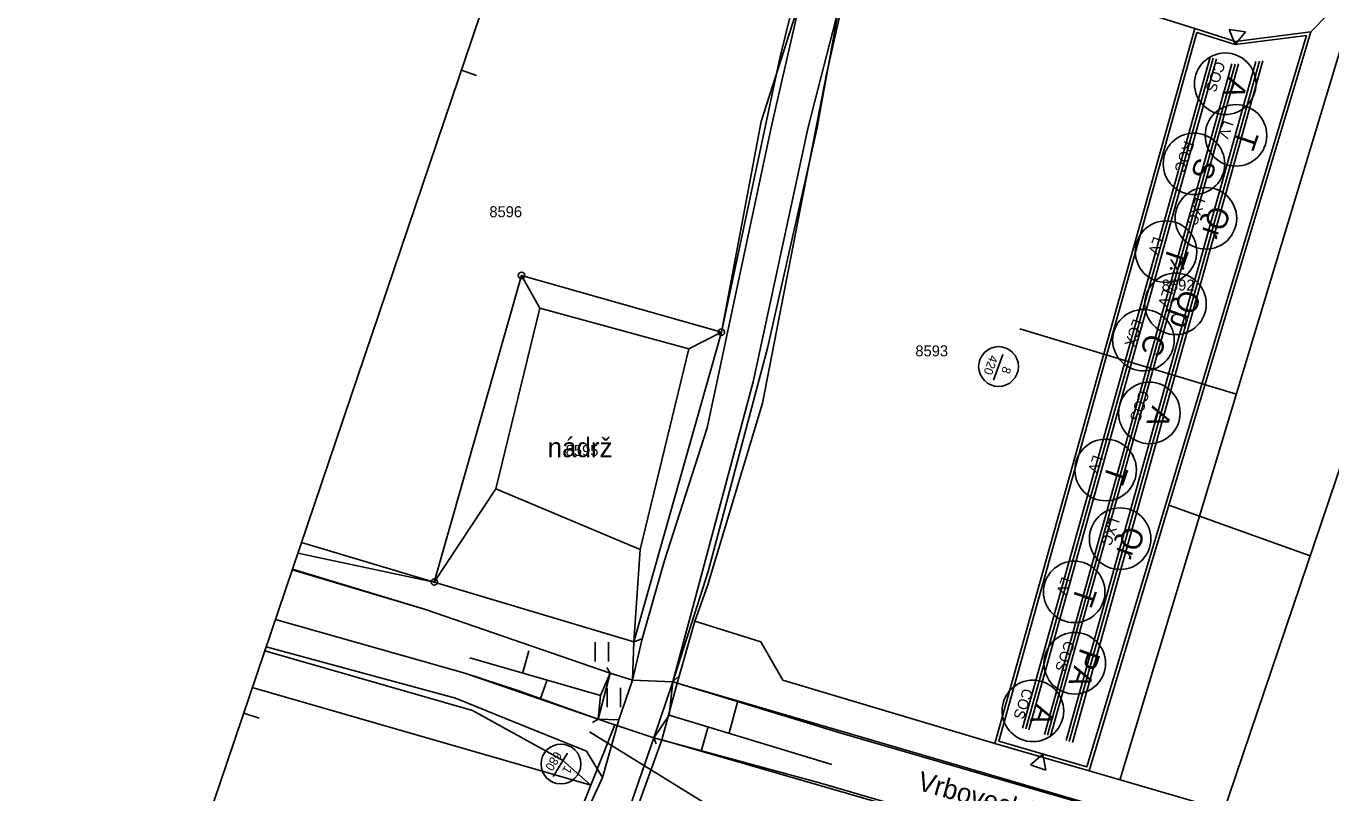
# Model space of a CAD drawing. Extents: x -639348 to -639039, y -1201065 to -1200521.
# Drawn here: x -639348.5 to -639146.6, y -1200930.7 to -1200812.1 of the extents above; entities that cross this region are included whole.
import ezdxf

# ---------------------------------------------------------------- set-up
doc = ezdxf.new("R2010")
doc.units = 0
for name, color, linetype in [('Hranice kat_ území', 7, 'Continuous'), ('Obvody jako plochy', 7, 'Continuous'), ('plot', 7, 'Continuous'), ('stromy', 7, 'Continuous'), ('trojrady', 7, 'Continuous'), ('tráva', 7, 'Continuous'), ('Vrstva 15', 7, 'Continuous'), ('Vrstva 18', 7, 'Continuous'), ('Vrstva 24', 7, 'Continuous'), ('Vrstva 25', 7, 'Continuous'), ('Vrstva 26', 7, 'Continuous'), ('Vrstva 43', 7, 'Continuous'), ('Vrstva 44', 7, 'Continuous'), ('Vrstva 45', 7, 'Continuous'), ('Vrstva 47', 7, 'Continuous'), ('Vrstva 48', 7, 'Continuous'), ('Vrstva 62', 7, 'Continuous'), ('Vrstva 63', 7, 'Continuous'), ('značky', 7, 'Continuous'), ('ŘEŠENÉ', 7, 'Continuous')]:
    doc.layers.add(name, color=color, linetype=linetype)

msp = doc.modelspace()

# ---------------------------------------------------------------- linework, layer by layer
at = {"layer": 'Hranice kat_ území'}
for p, q in [((-639259.95, -1200919.32), (-639258.12, -1200912.21)), ((-639248.38, -1200913.54), (-639251.32, -1200922.19))]:
    msp.add_line(p, q, dxfattribs=at)
at = {"layer": 'Obvody jako plochy'}
for p, q in [((-639167.64, -1200812.46), (-639207.36, -1200799.96)), ((-639229.15, -1200805.96), (-639231.84, -1200817.07)), ((-639142.08, -1200805.09), (-639149.66, -1200812.96)), ((-639222.04, -1200808.14), (-639224.6, -1200819.52)), ((-639198.57, -1200923.08), (-639167.64, -1200812.46)), ((-639149.66, -1200812.96), (-639171.65, -1200886.21)), ((-639167.64, -1200812.46), (-639161.32, -1200814.45)), ((-639161.32, -1200814.45), (-639149.66, -1200812.96)), ((-639231.84, -1200817.07), (-639240.89, -1200859.46)), ((-639224.6, -1200819.52), (-639234.5, -1200870.43)), ((-639271.82, -1200850.66), (-639285.31, -1200898.1)), ((-639240.89, -1200859.46), (-639271.82, -1200850.66)), ((-639254.43, -1200907.37), (-639240.89, -1200859.46)), ((-639234.5, -1200870.43), (-639243.04, -1200898.7)), ((-639184, -1200927.32), (-639171.65, -1200886.21)), ((-639171.65, -1200886.21), (-639149.78, -1200894.03)), ((-639285.31, -1200898.1), (-639305.87, -1200892)), ((-639307.3, -1200896.22), (-639286.68, -1200902.33)), ((-639285.31, -1200898.1), (-639254.43, -1200907.37)), ((-639243.04, -1200898.7), (-639245.01, -1200904.18)), ((-639286.68, -1200902.33), (-639258.12, -1200912.21)), ((-639309.89, -1200903.88), (-639280.61, -1200912.21)), ((-639245.01, -1200904.18), (-639247.74, -1200913.73)), ((-639245.01, -1200904.18), (-639234.76, -1200907.38)), ((-639254.43, -1200907.37), (-639254.64, -1200913.28)), ((-639234.76, -1200907.38), (-639231.36, -1200913.29)), ((-639279.41, -1200918), (-639311.54, -1200908.75)), ((-639280.61, -1200912.21), (-639259.95, -1200919.32)), ((-639254.64, -1200913.28), (-639258.12, -1200912.21)), ((-639254.64, -1200913.28), (-639248.38, -1200913.54)), ((-639247.74, -1200913.73), (-639250.09, -1200922.53)), ((-639248.38, -1200913.54), (-639247.74, -1200913.73)), ((-639247.74, -1200913.73), (-639164.68, -1200938.04)), ((-639231.36, -1200913.29), (-639198.57, -1200923.08)), ((-639261.1, -1200929.51), (-639313.47, -1200914.44)), ((-639265.47, -1200925.64), (-639279.41, -1200918)), ((-639259.95, -1200919.32), (-639257.38, -1200920.18)), ((-639257.38, -1200920.18), (-639261.1, -1200929.51)), ((-639251.32, -1200922.19), (-639257.38, -1200920.18)), ((-639253.49, -1200931.95), (-639250.09, -1200922.53)), ((-639251.32, -1200922.19), (-639250.09, -1200922.53)), ((-639250.09, -1200922.53), (-639167.48, -1200946.33)), ((-639184, -1200927.32), (-639198.57, -1200923.08)), ((-639261.1, -1200929.51), (-639265.47, -1200925.64)), ((-639163.1, -1200933.38), (-639184, -1200927.32)), ((-639261.1, -1200929.51), (-639263.57, -1200935.72))]:
    msp.add_line(p, q, dxfattribs=at)
at = {"layer": 'plot'}
for p, q in [((-639162.31, -1200812.6), (-639159.79, -1200812.97)), ((-639161.37, -1200814.96), (-639162.31, -1200812.6)), ((-639159.79, -1200812.97), (-639161.37, -1200814.96)), ((-639191.15, -1200924.72), (-639193.07, -1200926.38)), ((-639190.67, -1200927.22), (-639191.15, -1200924.72)), ((-639193.07, -1200926.38), (-639190.67, -1200927.22))]:
    msp.add_line(p, q, dxfattribs=at)
msp.add_lwpolyline([(-639167.3, -1200813.09), (-639161.37, -1200814.96), (-639150.36, -1200813.55), (-639172.13, -1200886.07), (-639184.34, -1200926.7), (-639197.96, -1200922.74)], close=True, dxfattribs=at)
at = {"layer": 'stromy'}
for centre in [(-639162.92, -1200821.01), (-639161.26, -1200829), (-639167.76, -1200833.4), (-639165.91, -1200841.83), (-639172.08, -1200846.99), (-639170.61, -1200855.07), (-639175.58, -1200860.68), (-639174.66, -1200871.94), (-639181.43, -1200880.77), (-639179.19, -1200891.4), (-639186.29, -1200899.63), (-639186.21, -1200910.67), (-639192.68, -1200918.04)]:
    msp.add_circle(centre, 4.76, dxfattribs=at)
at = {"layer": 'trojrady'}
for points in [[(-639194.27, -1200920.69), (-639165.24, -1200816.88)], [(-639193.79, -1200920.83), (-639164.77, -1200817.03)], [(-639193.31, -1200920.97), (-639164.29, -1200817.18)], [(-639190.91, -1200921.67), (-639161.9, -1200817.94)], [(-639190.43, -1200921.8), (-639161.4, -1200817.99)], [(-639189.95, -1200921.94), (-639160.86, -1200817.92)], [(-639187.55, -1200922.64), (-639158.17, -1200817.58)], [(-639187.07, -1200922.78), (-639157.63, -1200817.51)], [(-639186.58, -1200922.92), (-639157.09, -1200817.44)]]:
    msp.add_lwpolyline(points, dxfattribs=at)
at = {"layer": 'tráva'}
for p, q in [((-639167.64, -1200812.46), (-639198.57, -1200923.08)), ((-639171.65, -1200886.21), (-639149.66, -1200812.96)), ((-639161.32, -1200814.45), (-639167.64, -1200812.46)), ((-639149.66, -1200812.96), (-639161.32, -1200814.45)), ((-639184, -1200927.32), (-639171.65, -1200886.21)), ((-639198.57, -1200923.08), (-639184, -1200927.32))]:
    msp.add_line(p, q, dxfattribs=at)
at = {"layer": 'Vrstva 24'}
for centre, radius in [((-639271.82, -1200850.66), 0.5), ((-639271.82, -1200850.66), 0.0327), ((-639240.89, -1200859.46), 0.5), ((-639240.89, -1200859.46), 0.0327), ((-639285.31, -1200898.1), 0.5), ((-639285.31, -1200898.1), 0.0327)]:
    msp.add_circle(centre, radius, dxfattribs=at)
at = {"layer": 'Vrstva 25'}
for p, q in [((-639260.4, -1200907.4), (-639260.4, -1200910.4)), ((-639258.36, -1200910.4), (-639258.36, -1200907.4)), ((-639258.56, -1200914.48), (-639258.56, -1200917.48)), ((-639256.52, -1200917.48), (-639256.52, -1200914.48))]:
    msp.add_line(p, q, dxfattribs=at)
msp.add_lwpolyline([(-639169.36, -1200848.18), (-639170.36, -1200849.68), (-639171.36, -1200848.18)], dxfattribs=at)
for centre in [(-639171.27, -1200849.58), (-639169.47, -1200849.58)]:
    msp.add_circle(centre, 0.1, dxfattribs=at)
at = {"layer": 'Vrstva 26'}
for p, q in [((-639258.6, -1200911.34), (-639258.12, -1200912.21)), ((-639247.66, -1200912.84), (-639248.38, -1200913.54)), ((-639260.82, -1200919.82), (-639259.95, -1200919.32)), ((-639250.97, -1200923.13), (-639251.32, -1200922.19))]:
    msp.add_line(p, q, dxfattribs=at)
at = {"layer": 'Vrstva 43'}
for p, q in [((-639270.68, -1200908.73), (-639271.62, -1200912.11)), ((-639268.89, -1200916.1), (-639267.9, -1200913.37)), ((-639238.37, -1200916.71), (-639239.66, -1200921.44)), ((-639244.01, -1200924.27), (-639242.97, -1200920.65))]:
    msp.add_line(p, q, dxfattribs=at)
at = {"layer": 'Vrstva 44'}
for p, q in [((-639234.73, -1200826.87), (-639228.4, -1200807.02)), ((-639222.68, -1200809.05), (-639226.11, -1200828.06)), ((-639240.89, -1200859.46), (-639234.73, -1200826.87)), ((-639226.11, -1200828.06), (-639233.74, -1200861.94)), ((-639271.82, -1200850.66), (-639285.31, -1200898.1)), ((-639240.89, -1200859.46), (-639271.82, -1200850.66)), ((-639271.82, -1200850.66), (-639268.96, -1200855.72)), ((-639268.96, -1200855.72), (-639275.77, -1200883.7)), ((-639245.93, -1200862.03), (-639268.96, -1200855.72)), ((-639254.43, -1200907.37), (-639240.89, -1200859.46)), ((-639245.93, -1200862.03), (-639240.89, -1200859.46)), ((-639253.44, -1200893.06), (-639245.93, -1200862.03)), ((-639233.74, -1200861.94), (-639242.95, -1200896.48)), ((-639285.31, -1200898.1), (-639275.77, -1200883.7)), ((-639275.77, -1200883.7), (-639253.44, -1200893.06)), ((-639306.43, -1200893.64), (-639285.31, -1200898.1)), ((-639253.44, -1200893.06), (-639254.43, -1200907.37)), ((-639242.95, -1200896.48), (-639248.38, -1200913.54)), ((-639285.31, -1200898.1), (-639254.43, -1200907.37)), ((-639254.43, -1200907.37), (-639253.17, -1200906.88)), ((-639282.05, -1200916.07), (-639311.34, -1200908.15)), ((-639258.12, -1200912.21), (-639254.64, -1200913.28)), ((-639282.05, -1200916.07), (-639274.28, -1200919.24)), ((-639261.74, -1200924.29), (-639274.28, -1200919.24)), ((-639256.76, -1200919.44), (-639259.95, -1200919.32)), ((-639259.26, -1200928.33), (-639261.74, -1200924.29))]:
    msp.add_line(p, q, dxfattribs=at)
at = {"layer": 'Vrstva 45'}
for p, q in [((-639307.27, -1200896.13), (-639286.68, -1200902.33)), ((-639286.68, -1200902.33), (-639258.12, -1200912.21)), ((-639280.61, -1200912.21), (-639309.89, -1200903.88)), ((-639280.61, -1200912.21), (-639272.56, -1200914.81)), ((-639248.38, -1200913.54), (-639222.21, -1200921.52)), ((-639272.56, -1200914.81), (-639259.95, -1200919.32)), ((-639222.21, -1200921.52), (-639164.73, -1200938.2)), ((-639251.32, -1200922.19), (-639225.72, -1200929.17)), ((-639167.41, -1200946.1), (-639225.72, -1200929.17))]:
    msp.add_line(p, q, dxfattribs=at)
at = {"layer": 'Vrstva 47'}
for p, q in [((-639228.4, -1200807.02), (-639233.06, -1200827.31)), ((-639227.46, -1200827.75), (-639222.68, -1200809.05)), ((-639243.08, -1200874.26), (-639233.06, -1200827.31)), ((-639227.46, -1200827.75), (-639235.98, -1200867.14)), ((-639235.98, -1200867.14), (-639248.38, -1200913.54)), ((-639249.67, -1200894.79), (-639243.08, -1200874.26)), ((-639249.67, -1200894.79), (-639253.17, -1200906.88)), ((-639253.17, -1200906.88), (-639254.64, -1200913.28)), ((-639256.76, -1200919.44), (-639254.64, -1200913.28)), ((-639256.76, -1200919.44), (-639259.26, -1200928.33)), ((-639256.81, -1200938.01), (-639251.32, -1200922.19)), ((-639259.26, -1200928.33), (-639262.81, -1200935.98))]:
    msp.add_line(p, q, dxfattribs=at)
at = {"layer": 'Vrstva 48'}
for p, q in [((-639258.12, -1200912.21), (-639259.95, -1200919.32)), ((-639251.32, -1200922.19), (-639248.38, -1200913.54))]:
    msp.add_line(p, q, dxfattribs=at)
at = {"layer": 'Vrstva 62'}
for p, q in [((-639259.58, -1200915.66), (-639279.82, -1200909.85)), ((-639258.12, -1200912.21), (-639259.58, -1200915.66)), ((-639248.38, -1200913.54), (-639248.99, -1200918.7)), ((-639259.58, -1200915.66), (-639259.95, -1200919.32)), ((-639248.99, -1200918.7), (-639251.32, -1200922.19)), ((-639248.99, -1200918.7), (-639223.8, -1200926.34))]:
    msp.add_line(p, q, dxfattribs=at)
at = {"layer": 'Vrstva 63'}
for p, q in [((-639281.12, -1200818.92), (-639278.76, -1200819.72)), ((-639314.8, -1200918.37), (-639312.43, -1200919.18))]:
    msp.add_line(p, q, dxfattribs=at)
msp.add_lwpolyline([(-639180.1, -1200520.56), (-639348.48, -1201017.83), (-639207.82, -1201065.45), (-639039.44, -1200568.19)], close=True, dxfattribs=at)
at = {"layer": 'značky'}
for p, q in [((-639194.71, -1200858.95), (-639161.2, -1200869.06)), ((-639197.34, -1200862.89), (-639198.76, -1200866.88)), ((-639261.29, -1200921.28), (-639231.5, -1200939.66)), ((-639264.68, -1200924.58), (-639266.91, -1200928.18))]:
    msp.add_line(p, q, dxfattribs=at)
msp.add_lwpolyline([(-639074.59, -1200581.97), (-639179.21, -1200928.76)], dxfattribs=at)
for centre in [(-639198, -1200864.76), (-639265.72, -1200926.27)]:
    msp.add_circle(centre, 3.08, dxfattribs=at)
at = {"layer": 'ŘEŠENÉ'}
for p, q in [((-639167.64, -1200812.46), (-639198.57, -1200923.08)), ((-639171.65, -1200886.21), (-639149.66, -1200812.96)), ((-639161.32, -1200814.45), (-639167.64, -1200812.46)), ((-639149.66, -1200812.96), (-639161.32, -1200814.45)), ((-639184, -1200927.32), (-639171.65, -1200886.21)), ((-639198.57, -1200923.08), (-639184, -1200927.32))]:
    msp.add_line(p, q, dxfattribs=at)

# ---------------------------------------------------------------- texts
at = {"layer": 'stromy'}
for s, height, p in [('COS', 1.651, (-639164.42, -1200817.4)), ('A', 3.3, (-639162.44, -1200819.79)), ('LV', 1.651, (-639163.16, -1200826.57)), ('T', 3.3, (-639160.82, -1200827.91)), ('ROC', 1.651, (-639169.23, -1200829.72)), ('S', 3.3, (-639167.31, -1200832.27)), ('LXC', 1.651, (-639167.49, -1200838.45)), ('Qr', 3.302, (-639165.1, -1200839.67)), ('LV', 1.651, (-639173.98, -1200844.55)), ('T', 3.3, (-639171.63, -1200845.89)), ('LV', 1.651, (-639172.51, -1200852.64)), ('Qp', 3.302, (-639169.7, -1200852.63)), ('LCX', 1.651, (-639177.14, -1200857.27)), ('C', 3.3, (-639175.09, -1200859.44)), ('COS', 1.651, (-639176.16, -1200868.33)), ('A', 3.3, (-639174.18, -1200870.72)), ('LV', 1.651, (-639183.33, -1200878.34)), ('T', 3.3, (-639180.99, -1200879.68)), ('LXC', 1.651, (-639180.77, -1200888.02)), ('Qr', 3.302, (-639178.38, -1200889.24)), ('LV', 1.651, (-639188.19, -1200897.19)), ('T', 3.3, (-639185.85, -1200898.53)), ('COS', 1.651, (-639187.71, -1200907.06)), ('PA', 3.302, (-639185.28, -1200908.16)), ('COS', 1.651, (-639194.17, -1200914.43)), ('A', 3.3, (-639192.19, -1200916.82))]:
    msp.add_text(s, height=height, rotation=250.8987, dxfattribs=at).set_placement(p)
at = {"layer": 'Vrstva 15'}
msp.add_text('nádrž', height=3, dxfattribs=at).set_placement((-639267.77, -1200878.79))
msp.add_text('Vrbovecký potok', height=3, rotation=344.388, dxfattribs=at).set_placement((-639210.74, -1200930.22))
at = {"layer": 'Vrstva 18'}
for s, p in [('8596', (-639276.79, -1200841.66)), ('8592', (-639172.74, -1200853.01)), ('8593', (-639210.87, -1200863.19)), ('8595', (-639264.97, -1200878.59))]:
    msp.add_text(s, height=1.7, dxfattribs=at).set_placement(p)
at = {"layer": 'značky'}
for s, height, rotation, p in [('420', 1.355, 250.3836, (-639199.32, -1200862.9)), ('8', 1.35, 250.3836, (-639197.27, -1200864.64)), ('680', 1.355, 238.3141, (-639266.62, -1200924.18)), ('1', 1.35, 238.3141, (-639265.05, -1200926.42))]:
    msp.add_text(s, height=height, rotation=rotation, dxfattribs=at).set_placement(p)

doc.saveas('drawing.dxf')
